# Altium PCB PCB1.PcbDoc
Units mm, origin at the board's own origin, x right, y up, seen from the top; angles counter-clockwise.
Board outline 152.4 x 101.6 mm, 2 copper layers (Top Layer, Bottom Layer); 27 components, 17 nets, 70 pads, 0 vias.
Unrouted connection lines stored in the file: 49.
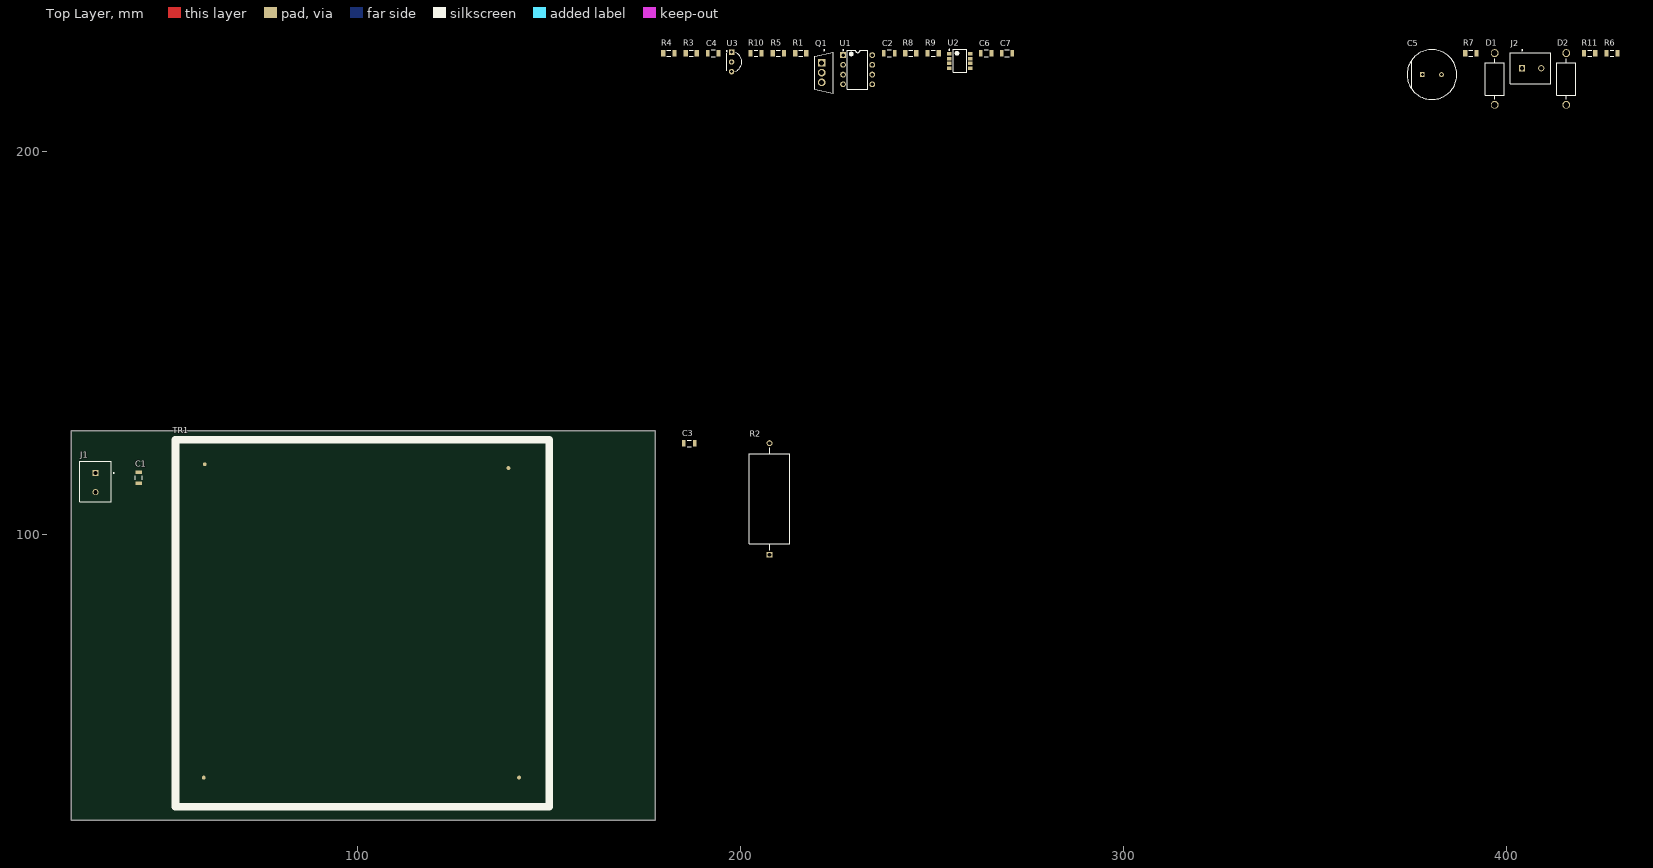
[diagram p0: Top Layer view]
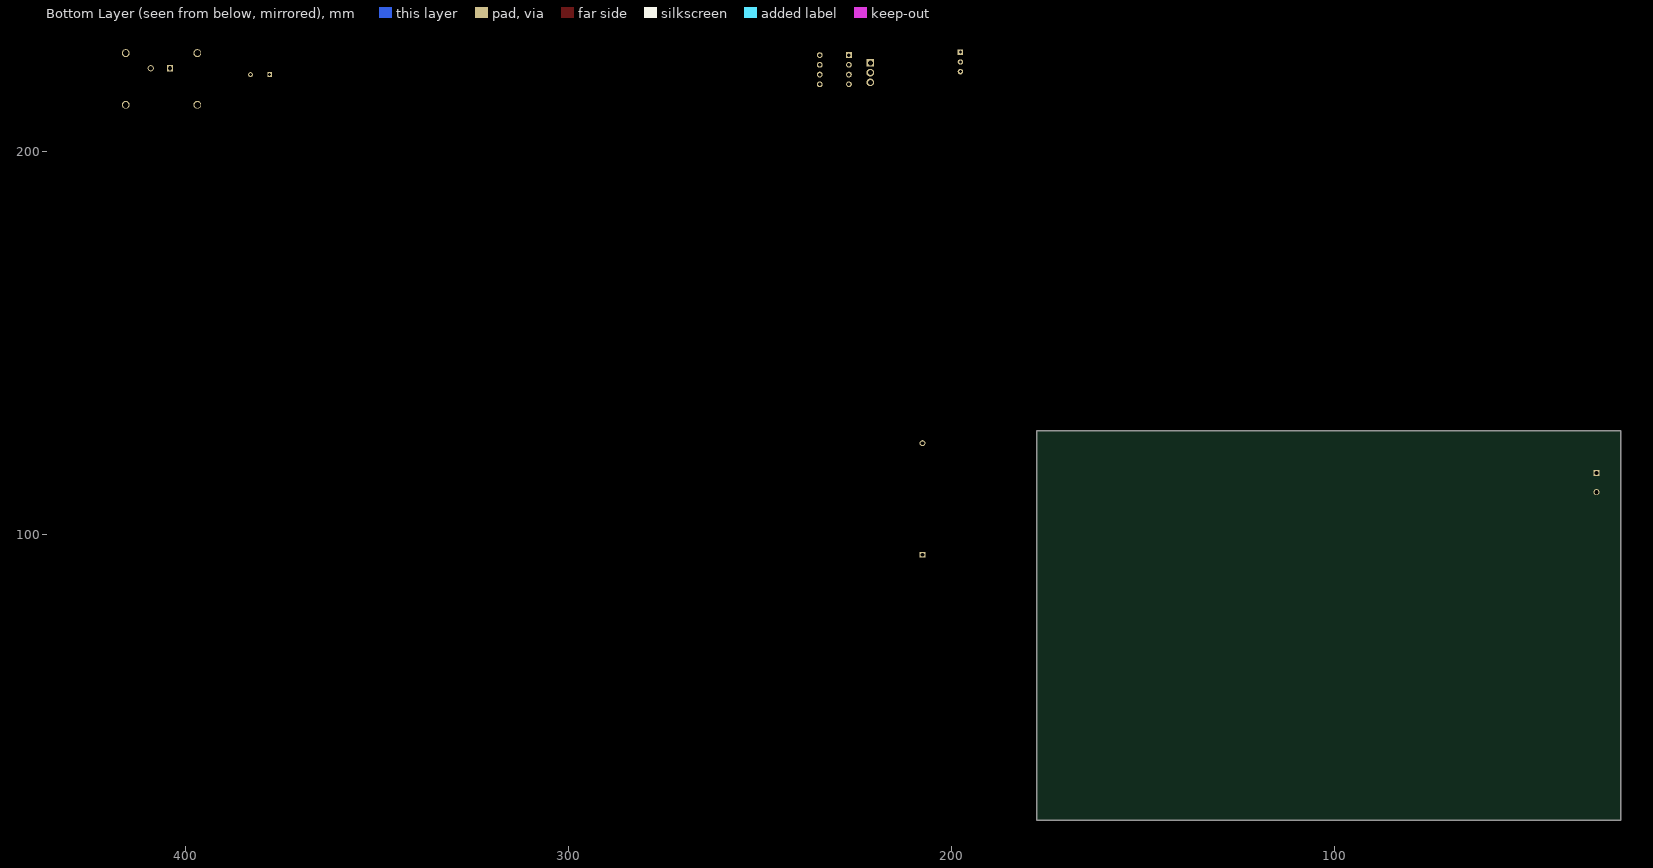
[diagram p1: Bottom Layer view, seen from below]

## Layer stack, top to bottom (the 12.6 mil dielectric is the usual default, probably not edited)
Top Solder: solder mask 0.0102, Solder Resist, Dk 3.5
Top Layer: signal copper 0.0356
Dielectric 1: dielectric 0.32, FR-4, Dk 4.8
Bottom Layer: signal copper 0.0356
Bottom Solder: solder mask 0.0102, Solder Resist, Dk 3.5

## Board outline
25.4,25.4 177.8,25.4 177.8,127 25.4,127

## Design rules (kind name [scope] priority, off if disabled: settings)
Clearance [All] p1: gap=0.254 ignorepadtopadclearanceinfootprint=FALSE except(0: Arc-Hole Track-Hole SMDPad-Hole THPad-Hole Via-Hole Fill-Hole Poly-Hole Region-Hole Text-Hole)
PolygonConnect [All] p1: connectstyle=Relief reliefconductorwidth=0.254 reliefentries=4 polygonreliefangle="90 Angle" airgapwidth=0.254
RoutingVias [All] p1: holewidth=0.711 width=1.27 viastyle="Through Hole" minholewidth=0.711 minwidth=1.27 maxholewidth=0.711 maxwidth=1.27
SolderMaskExpansion [All] p1: expansion=0.102 istentingtop=FALSE
Width [All] p1: maxlimit=0.254 minlimit=0.254 preferedwidth=0.254
30 further rules are at their usual default settings.

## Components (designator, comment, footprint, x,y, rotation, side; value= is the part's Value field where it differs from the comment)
C1 "4.7uF (1206)" FP-C1206C-EB-MFG 43,114.75 r270 top value="1,000 pF"
C2 "1nF (1206)" FP-C1206C-EB-MFG 238.887,225.552 r0 top value="1,000 pF"
C3 "4.7uF (1206)" FP-C1206C-EB-MFG 186.69,123.698 r0 top value="1,000 pF"
C4 "1nF (1206)" FP-C1206C-EB-MFG 192.913,225.552 r0 top value="1,000 pF"
C5 "CAP 100uF UBX2A101MHL" FP-UBX2A101MHL-MFG 380.492,219.964 r0 top value=100uF
C6 "20uF (1206)" FP-C1206C-EB-MFG 264.16,225.552 r0 top value="1,000 pF"
C7 "1nF (1206)" FP-C1206C-EB-MFG 269.621,225.552 r0 top value="1,000 pF"
D1 "Schottky (MBR3100RLG)" ONSC-AXIAL_LEAD-2-267-05_V 396.875,218.821 r90 top
D2 "MUR460" ONSC-AXIAL_LEAD-2-267-05_V 415.544,218.821 r90 top
J1 "282836-2" TECO-282836-2_V 31.75,113.5 r270 top
J2 "282836-2" TECO-282836-2_V 406.527,221.615 r0 top
Q1 "IRFI540N (TO-220)" FP-PG-TO220-3-MFG 221.869,220.472 r0 top
R1 "10k Ohm (1206)" RESC3216X60X45NL10T20 215.773,225.552 r0 top
R2 "5W (300-1k Ohm)" FP-SQP500-MFG 207.645,109.22 r90 top value=1.2Ω
R3 "4.99k Ohm (1206)" RESC3216X60X45NL10T20 187.198,225.552 r0 top
R4 "7.68k Ohm (1206)" RESC3216X60X45NL10T20 181.356,225.552 r0 top
R5 "8.66k Ohm (1206)" RESC3216X60X45NL10T20 209.931,225.552 r0 top
R6 "6k Ohm (1206)" RESC3216X60X45NL10T20 427.482,225.552 r0 top
R7 "3k Ohm (1206)" RESC3216X60X45NL10T20 390.652,225.552 r0 top
R8 "13.7k Ohm (1206)" RESC3216X60X45NL10T20 244.475,225.552 r0 top
R9 "15.4k Ohm (1206)" RESC3216X60X45NL10T20 250.317,225.552 r0 top
R10 "3.01k Ohm (1206)" RESC3216X60X45NL10T20 204.089,225.552 r0 top
R11 "54.9k Ohm (1206)" RESC3216X60X45NL10T20 421.64,225.552 r0 top
TR1 "transformer" Transformer_flyback 60.25,36.25 r0 top
U1 "UC3845N" P0008A 230.632,221.234 r0 top
U2 "ILD217T (SOIC-8)" VISH-SOIC-8_C_V 257.302,223.52 r0 top
U3 "TL431ILP (TO92-3)" LP0003A 197.739,223.266 r0 top

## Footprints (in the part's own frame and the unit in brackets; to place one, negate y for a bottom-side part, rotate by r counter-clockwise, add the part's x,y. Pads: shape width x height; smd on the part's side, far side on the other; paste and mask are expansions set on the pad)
FP-C1206C-EB-MFG [mm]
  rect 0.95x1.7 smd paste+0 mask+0: 1(-1.4,0) 2(1.4,0)
  silkscreen extent -0.55,-0.9 0.55,0.9, body extent -2,-1 2,1, height 0.25
FP-PG-TO220-3-MFG [mm]
  rect 2x2 hole 1.3 paste-1000 mask+0: 1(-0.61,2.54)
  round 2 hole 1.3 paste-1000 mask+0: 2(-0.61,0) 3(-0.61,-2.54)
  silkscreen extent -2.41,-5.38 2.41,6, body extent -2.51,-5.6 2.51,5.6, height 0.25
FP-SQP500-MFG [mm]
  rect 1.55x1.55 hole 1 paste-1000 mask+0: 1(-14.555,0)
  round 1.55 hole 1 paste-1000 mask+0: 2(14.555,0)
  silkscreen extent -13.38,-5.25 13.38,5.25, body extent -15.43,-5.35 15.43,5.35, height 0.25
FP-UBX2A101MHL-MFG [mm]
  rect 1.25x1.25 hole 0.75 paste-1000 mask+0: 1(-2.5,0)
  round 1.25 hole 0.75 paste-1000 mask+0: 2(2.5,0)
  silkscreen extent -6.5,-6.5 6.5,6.5, body extent -6.6,-6.6 6.6,6.6, height 0.25
LP0003A [mm] "TO, Flat Index; 3 In-Line, Formed Axial Leads; Body Dia. 4.8mm; Leads 0.56 x 0.41 mm (max)"
  rrect7% 1.4x1.4 hole 0.8: 1(0,2.54)
  round 1.4 hole 0.8: 2(0,0) 3(0,-2.54)
  silkscreen extent -1.35,-2.41 2.65,2.95, body extent -1.33,-2.83 2.35,2.83, height 9.01
ONSC-AXIAL_LEAD-2-267-05_V [mm] "AXIAL, 2-Leads, Diameter 5.05mm"
  round 2.05 hole 1.55: 1(-6.745,0) 2(6.745,0)
  silkscreen extent -5.32,-2.52 5.32,2.52
P0008A [mm] "DIP, 8-Leads, Body 10.15x6.6mm, Pitch 2.54mm"
  rect 1.5x1.5 hole 0.9: 1(-3.81,3.81)
  round 1.5 hole 0.9: 2(-3.81,1.27) 3(-3.81,-1.27) 4(-3.81,-3.81) 5(3.81,-3.81) 6(3.81,-1.27) 7(3.81,1.27) 8(3.81,3.81)
  silkscreen extent -3.93,-5.1 2.65,5.23, body extent -3.95,-5.07 3.95,5.07, height 5.08
RESC3216X60X45NL10T20 [mm] "Chip Resistor, 2-Leads, Body 3.20x1.60mm, IPC Medium Density"
  rect 1.1x1.7 smd: 1(-1.45,0) 2(1.45,0)
  silkscreen extent -0.5,-0.75 0.5,0.75, body extent -1.65,-0.85 1.65,0.85, height 0.6
TECO-282836-2_V [mm] "Female Header, Pitch 5mm, 1 x 2 Position, Height 10mm"
  rect 1.6x1.6 hole 1.1: 1(-2.5,0)
  round 1.6 hole 1.1: 2(2.5,0)
  silkscreen extent -5.6,-4.1 5,4.88, body extent -5.6,-4.1 5,4.1, height 10
Transformer_flyback [mil]
  round 40 smd mask+100: 1(0,3230) 2(-10,10) 3(3120,3190) 4(3230,10)
  silkscreen extent -300,-290 3540,3480
VISH-SOIC-8_C_V [mm] "SOIC, 8-Leads, Body 6x4mm, Pitch 1.27mm"
  rect 1.14x0.91 smd: 1(-2.73,1.905) 2(-2.73,0.635) 3(-2.73,-0.635) 4(-2.73,-1.905) 5(2.73,-1.905) 6(2.73,-0.635) 7(2.73,0.635) 8(2.73,1.905)
  silkscreen extent -2.85,-3 1.75,3.03, body extent -3,-3 3,3, height 3.46

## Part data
C1 C2 C3 C4 C6 C7: library part CMP-03020-000955-1, "Multilayer Ceramic Capacitor, C Series, 1000 Pf, - 5%, C0g / Np0, 100 V, 1206 [3216 Metric] Rohs Compliant: Yes", Capacitance="1,000 pF", Manufacturer=KEMET, Manufacturer Part Number=C1206C102J1GACTU, Package=C1206C-EB, Temperature="-55°C to +150°C", Temperature Characteristic=C0G, Temperature Coefficient=15%, Temperature Range High=+150°C, Temperature Range Low=-55°C, Tolerance=0.05, Voltage Rating="100 V"
C5: library part CMP-12462-000004-1, "CAP ALUM 100UF 20% 100V RADIAL", Capacitance=100uF, Leakage Current=300uA, Manufacturer=Nichicon, Manufacturer Part Number=UBX2A101MHL, Package=0, Ripple Current=950mA, Temperature="-55°C to +150°C", Temperature Range High=+150°C, Temperature Range Low=-55°C, Tolerance=20%, Voltage Rating=100V
D1: library part CMP-1055-00020-1, "Rectifier, 2-Pin Axial_Lead, Pb-Free, Tape and Reel", Manufacturer="On Semiconductor", PartNumber=MBR3100RLG
D2: library part CMP-0902-00067-1, "SWITCHMODE(TM) Power Rectifier, 2-Pin Axial_Lead, Pb-Free, Bulk Bag", Manufacturer="On Semiconductor"
J1 J2: library part CMP-1684-00017-1, "Female Header, Pitch 5 mm, 1 x 2 Position, Height 10 mm, Tail Length 3.5 mm, Rohs, Bulk", Color=Green, Current=13.5A, Manufacturer="TE Connectivity", Package Description="Female Header, Pitch 5 mm, 1 x 2 Position, Height 10 mm, Tail Length 3.5 mm", Package Reference=THD, Standard Package=300, Voltage=300V
Q1: library part CMP-32901-000575-1, "MOSFET N-CH 100V 20A TO220FP", Case/Package=TO-220-3, Continuous Drain Current (ID)=20A, Drain to Source Breakdown Voltage=100V, Drain to Source Resistance=52mR, Gate to Source Voltage (Vgs)=20V, Max Operating Temperature=175°C, Max Power Dissipation=54W, Min Operating Temperature=-55°C, Threshold Voltage=4V, Input Capacitance=1.4nF
R1 R3 R4 R5 R6 R7 R8 R9 R10 R11: library part CMP-2003-02424-1, Manufacturer="Vishay Dale", Part Number=CRCW12068R25FKEA
R2: library part CMP-03413-000003-1, Manufacturer=Yageo, Manufacturer Part Number=SQP500JB-1R2, Package=SQP500, Power Rating=5W, Resistance=1.2Ω, Temperature="-55°C to +155°C", Temperature Coefficient=300ppm/°C, Temperature Range High=+155°C, Temperature Range Low=-55°C, Tolerance=5%, Voltage Rating=350V
U1: library part CMP-0319-00305-2, "PWM Controller with Current Control, 50 % Duty Cycle, 0 to +70 degC, 8-pin PDIP (P), Green (RoHS & no Sb/Br)", Frequency(Max)(kHz)=450, Manufacturer="Texas Instruments", Rating=Catalog
U2: library part CMP-2000-06453-1, "Optocoupler, Phototransistor Output, Dual Channel, 4000 VRMS, -55 to 100 degC, 8-Pin SOIC, RoHS, Tape and Reel", Current - DC Forward (If) (Max)=30mA, Current - Output / Channel=-, Current Transfer Ratio (Max)=200%@10mA, Current Transfer Ratio (Min)=100%@10mA, Manufacturer=Vishay, Operating Temperature=-55°C~100°C, Package / Case="8-SOIC(0.154\",3.90mmWidth)", Package Description="8-Pin Small Outline Integrated Circuit, Body 5.84 x 3.91 mm, Pitch 1.27 mm", Package Reference=SOIC-8, Standard Package=1, Supplier Device Package=8-SOIC, Voltage - Forward (Vf) (Typ)=1.2V, Voltage - Output (Max)=70V, Voltage - Isolation=4000Vrms
U3: library part CMP-0366-00043-2, "Adjustable Precision Shunt Regulator, 34 ppm / degC, 100 mA, -40 to 85 degC, 3-pin TO-92 (LP), Pb-Free (RoHS)", Manufacturer="Texas Instruments", PartNumber=TL431ILP, Rating=Military, Temp Coeff(Max)(ppm/ degree C)=92, Temp Coeff(Typ)(ppm/ degree C)=34

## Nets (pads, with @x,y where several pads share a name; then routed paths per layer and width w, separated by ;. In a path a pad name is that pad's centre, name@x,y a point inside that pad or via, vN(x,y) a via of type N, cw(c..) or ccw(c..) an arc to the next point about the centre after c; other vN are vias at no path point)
GND: C1.2 C4.2 J1.2 Q1.3 R4.1 U1.3 U1.5
NetC1_1: C1.1 C3.1 J1.1 R2.1 TR1.1 U1.7
NetC2_1: C2.1 R1.2 R3.2 U1.2
NetC2_2: C2.2 R1.1 U1.1
NetC3_2: C3.2 D1.1 R2.2
NetC4_1: C4.1 R5.2 U1.4
NetC5_2: C5.2 C6.2 C7.2 D2.1 J2.1 R6.1 R11.1
NetD1_2: D1.2 Q1.2 TR1.2
NetD2_2: D2.2 TR1.3
NetQ1_1: Q1.1 U1.6
NetR3_1: R3.1 R4.2 U2.7
NetR5_1: R5.1 U1.8 U2.8
NetR6_2: R6.2 R7.1 R8.1 R9.1
NetR8_2: R8.2 U2.2 U3.3
NetR9_2: R9.2 U2.1
NetR10_1: R10.1 R11.2 U3.1
SGND: C5.1 C6.1 C7.1 J2.2 R7.2 R10.2 TR1.4 U3.2
pads on no net: U2.3 U2.4 U2.5 U2.6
